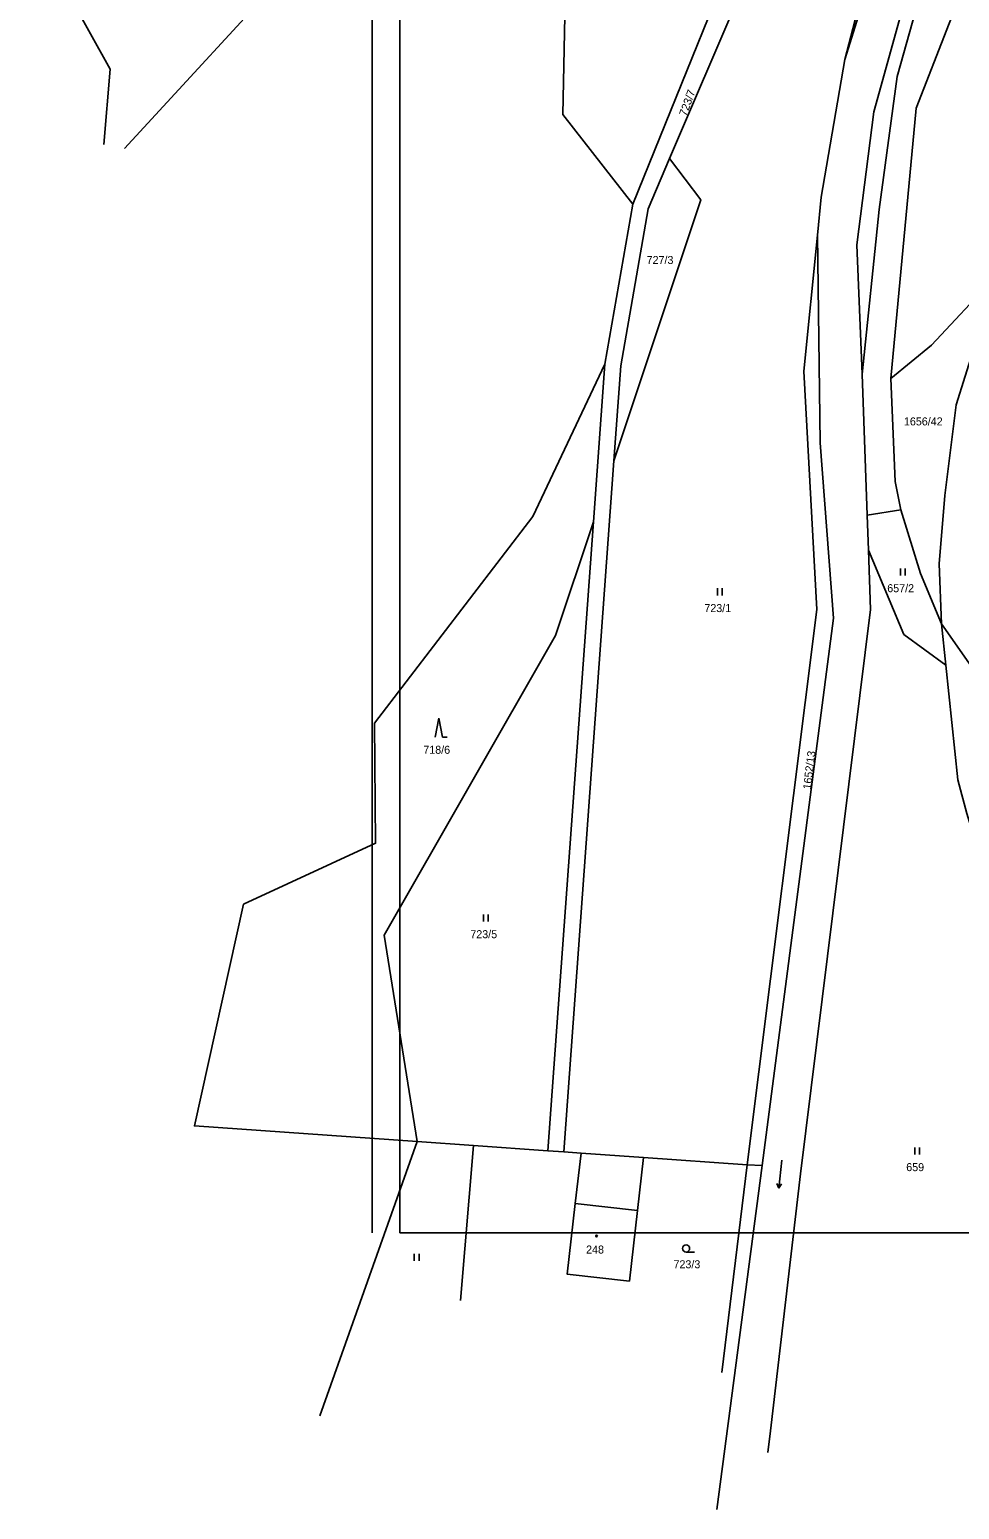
# Model space of a CAD drawing. Extents: x -553916 to -552953, y -1067469 to -1066637.
# Drawn here: x -553872.7 to -553675.3, y -1067469 to -1067154.7 of the extents above; entities that cross this region are included whole.
import ezdxf

# ---------------------------------------------------------------- set-up
doc = ezdxf.new("R2010")
doc.units = 0
for name, color, linetype in [('Hranice parcel', 7, 'Continuous'), ('Parcelní čísla', 7, 'Continuous'), ('Vnitřní kresba', 7, 'Continuous'), ('Vrstva 1', 7, 'Continuous'), ('Značky budov', 7, 'Continuous'), ('Značky kultur', 7, 'Continuous')]:
    doc.layers.add(name, color=color, linetype=linetype)

msp = doc.modelspace()

# ---------------------------------------------------------------- linework, layer by layer
at = {"layer": 'Hranice parcel'}
for p, q in [((-553682.64, -1067055.36), (-553736.85, -1067182.11)), ((-553699.64, -1067161.1), (-553692.26, -1067132.51)), ((-553744.69, -1067191.8), (-553750.62, -1067225.75)), ((-553750.62, -1067225.75), (-553753.04, -1067259.3)), ((-553695.94, -1067227.92), (-553694.89, -1067257.82)), ((-553748.69, -1067246.29), (-553759.3, -1067393.1)), ((-553694.89, -1067257.82), (-553687.76, -1067256.69)), ((-553762.69, -1067392.86), (-553753.04, -1067259.3)), ((-553694.89, -1067257.82), (-553694.63, -1067265.31)), ((-553678.21, -1067289.69), (-553679.12, -1067280.91)), ((-553675.68, -1067314.09), (-553678.21, -1067289.69)), ((-553790.46, -1067390.9), (-553811.08, -1067449.2)), ((-553790.46, -1067390.9), (-553778.49, -1067391.74)), ((-553778.49, -1067391.74), (-553781.25, -1067424.65)), ((-553762.69, -1067392.86), (-553778.49, -1067391.74)), ((-553759.3, -1067393.1), (-553762.69, -1067392.86)), ((-553759.3, -1067393.1), (-553755.65, -1067393.35)), ((-553742.38, -1067394.29), (-553755.65, -1067393.35)), ((-553742.38, -1067394.29), (-553720.38, -1067395.83)), ((-553717.22, -1067396.01), (-553726.82, -1067469.04)), ((-553725.77, -1067439.98), (-553720.38, -1067395.83)), ((-553720.38, -1067395.83), (-553717.22, -1067396.01))]:
    msp.add_line(p, q, dxfattribs=at)
for points in [[(-553648.57, -1066991.82), (-553659.32, -1067017.01), (-553678.4, -1067093.07), (-553699.64, -1067161.1)], [(-553695.94, -1067227.92), (-553697.09, -1067200.45), (-553693.46, -1067172.18), (-553652.47, -1067024.37)], [(-553856.98, -1067179.12), (-553855.63, -1067163.09), (-553864, -1067148.03), (-553860.02, -1067146.13), (-553872.73, -1067094.13), (-553844.72, -1067085.79), (-553834.37, -1067133.89), (-553804.82, -1067119.79), (-553771, -1067105.16), (-553739.65, -1067037.62)], [(-553655.53, -1067040.29), (-553660.05, -1067063.23), (-553688.55, -1067164.71), (-553692.38, -1067192.94), (-553695.94, -1067227.92)], [(-553691.88, -1067055.11), (-553698.79, -1067078.47), (-553744.69, -1067191.8)], [(-553648.45, -1067052.9), (-553657.29, -1067086.06), (-553666.21, -1067098.13), (-553670.52, -1067135.37), (-553684.51, -1067171.37), (-553689.91, -1067228.79)], [(-553852.6, -1067180), (-553815.54, -1067139.66), (-553779.26, -1067146.56), (-553772.79, -1067113.94), (-553753.66, -1067113.05), (-553758.92, -1067144.82), (-553759.49, -1067172.72), (-553744.69, -1067191.8)], [(-553705.47, -1067198.37), (-553704.66, -1067190.29), (-553699.64, -1067161.1)], [(-553748.69, -1067246.29), (-553747.24, -1067226.17), (-553741.4, -1067192.77), (-553736.85, -1067182.11)], [(-553736.85, -1067182.11), (-553730.23, -1067190.89), (-553748.69, -1067246.29)], [(-553689.91, -1067228.79), (-553681.28, -1067221.74), (-553667.99, -1067207.55), (-553660.17, -1067189.87)], [(-553660.17, -1067189.87), (-553665.44, -1067205.7), (-553670.26, -1067216.16), (-553675.98, -1067234.41), (-553678.44, -1067253.69), (-553679.63, -1067268.16), (-553679.12, -1067280.91)], [(-553720.38, -1067395.83), (-553705.59, -1067277.88), (-553708.38, -1067227.3), (-553705.47, -1067198.37)], [(-553717.22, -1067396.01), (-553702.06, -1067279.73), (-553704.85, -1067242.51), (-553705.47, -1067198.37)], [(-553750.62, -1067225.75), (-553765.92, -1067258.16), (-553799.48, -1067302.04), (-553799.26, -1067327.54), (-553827.3, -1067340.5), (-553837.73, -1067387.58), (-553790.46, -1067390.9)], [(-553687.76, -1067256.69), (-553688.96, -1067250.67), (-553689.91, -1067228.79)], [(-553679.12, -1067280.91), (-553683.6, -1067270.21), (-553687.76, -1067256.69)], [(-553753.04, -1067259.3), (-553761.11, -1067283.4), (-553797.47, -1067347.09), (-553790.46, -1067390.9)], [(-553694.63, -1067265.31), (-553694.19, -1067277.87), (-553709.03, -1067397.74), (-553715.41, -1067452.36), (-553716.03, -1067456.95)], [(-553694.63, -1067265.31), (-553687.13, -1067283.19), (-553678.21, -1067289.69)], [(-553679.12, -1067280.91), (-553661.1, -1067306.72), (-553656.17, -1067315.75)], [(-553654.47, -1067375.83), (-553662.26, -1067358.39), (-553673.71, -1067321.24), (-553675.68, -1067314.09)], [(-553755.65, -1067393.35), (-553756.88, -1067404.04), (-553758.6, -1067419.04), (-553745.39, -1067420.55), (-553743.67, -1067405.55), (-553742.38, -1067394.29)]]:
    msp.add_lwpolyline(points, dxfattribs=at)
at = {"layer": 'Vnitřní kresba'}
msp.add_line((-553756.88, -1067404.04), (-553743.67, -1067405.55), dxfattribs=at)
at = {"layer": 'Vrstva 1'}
for p, q in [((-553794.11, -1067410.27), (-553794.11, -1066816.27)), ((-552953.11, -1067410.27), (-553794.11, -1067410.27))]:
    msp.add_line(p, q, dxfattribs=at)
msp.add_lwpolyline([(-553800, -1067410.27), (-553800, -1067100), (-553300, -1067100), (-553300, -1067410.27)], dxfattribs=at)
at = {"layer": 'Značky budov'}
msp.add_circle((-553752.36, -1067410.97), 0.175, dxfattribs=at)
at = {"layer": 'Značky kultur'}
for p, q in [((-553687.85, -1067270.67), (-553687.85, -1067269.17)), ((-553686.85, -1067270.67), (-553686.85, -1067269.17)), ((-553726.68, -1067274.89), (-553726.68, -1067273.39)), ((-553725.68, -1067274.89), (-553725.68, -1067273.39)), ((-553785.84, -1067300.99), (-553786.59, -1067304.99)), ((-553785.09, -1067304.99), (-553785.84, -1067300.99)), ((-553785.09, -1067304.99), (-553784.09, -1067304.99)), ((-553776.37, -1067344.16), (-553776.37, -1067342.66)), ((-553775.37, -1067344.16), (-553775.37, -1067342.66)), ((-553713.04, -1067394.85), (-553713.66, -1067400.82)), ((-553684.8, -1067393.64), (-553684.8, -1067392.14)), ((-553683.8, -1067393.64), (-553683.8, -1067392.14)), ((-553713.66, -1067400.82), (-553714.06, -1067399.8)), ((-553713.66, -1067400.82), (-553713.06, -1067399.9)), ((-553791.05, -1067416.23), (-553791.05, -1067414.73)), ((-553790.05, -1067416.23), (-553790.05, -1067414.73)), ((-553733.35, -1067414.37), (-553731.6, -1067414.37))]:
    msp.add_line(p, q, dxfattribs=at)
msp.add_circle((-553733.35, -1067413.62), 0.75, dxfattribs=at)

# ---------------------------------------------------------------- texts
at = {"layer": 'Parcelní čísla'}
for s, rotation, p in [('723/7', 70, (-553733.29, -1067173.23)), ('1652/13', 83, (-553706.87, -1067316.2))]:
    msp.add_text(s, height=1.7, rotation=rotation, dxfattribs=at).set_placement(p)
for s, p in [('727/3', (-553741.73, -1067204.5)), ('1656/42', (-553687.1, -1067238.79)), ('657/2', (-553690.64, -1067274.22)), ('723/1', (-553729.47, -1067278.44)), ('718/6', (-553789.14, -1067308.54)), ('723/5', (-553779.16, -1067347.71)), ('659', (-553686.61, -1067397.19)), ('248', (-553754.58, -1067414.69)), ('723/3', (-553736.02, -1067417.82))]:
    msp.add_text(s, height=1.7, dxfattribs=at).set_placement(p)

doc.saveas('drawing.dxf')
